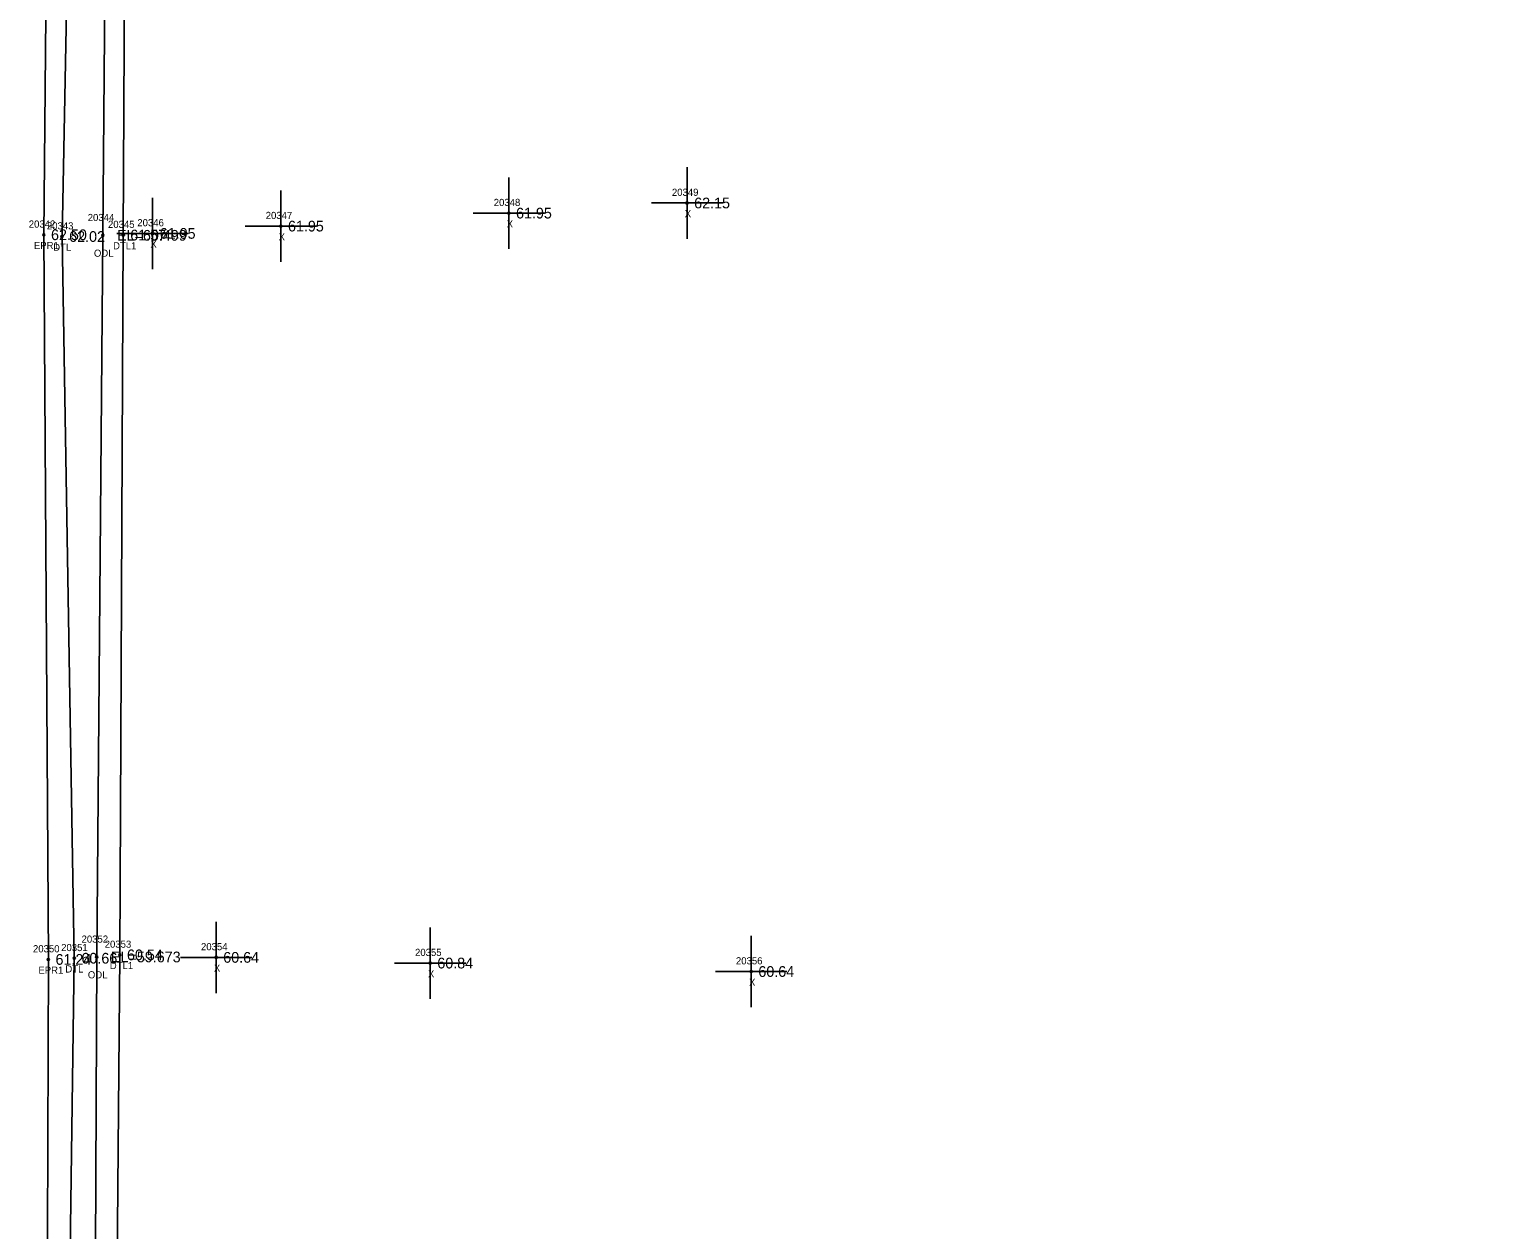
# Model space of a CAD drawing. Extents: x 2420351 to 2422725, y 845330 to 846558.
# Drawn here: x 2420969.7 to 2421174.5, y 845858.7 to 846026.9 of the extents above; entities that cross this region are included whole.
import ezdxf

# ---------------------------------------------------------------- set-up
doc = ezdxf.new("R2010")
doc.units = 0
for name, color, linetype in [('RD_EX_H2O', 7, 'Continuous'), ('RD_EX_H2O_txCode', 7, 'Continuous'), ('RD_EX_Misc', 7, 'Continuous'), ('RD_EX_Misc_txCode', 7, 'Continuous'), ('RD_EX_Road', 7, 'Continuous'), ('RD_EX_Road_txCode', 7, 'Continuous'), ('RD_EX_TX_H2O_ELEV', 7, 'Continuous'), ('RD_EX_TX_Misc_ELEV', 7, 'Continuous'), ('RD_EX_TX_Road_ELEV', 7, 'Continuous'), ('RD_SMD_Locator', 7, 'Continuous')]:
    doc.layers.add(name, color=color, linetype=linetype)

msp = doc.modelspace()

# ---------------------------------------------------------------- linework, layer by layer
at = {"layer": 'RD_EX_H2O'}
for points in [[(2420975.55, 846190.58), (2420976.37, 846105.11), (2420974.31, 845997.82), (2420976.03, 845896.74), (2420974.59, 845794.18), (2420975.37, 845743.63), (2420984.12, 845720.99), (2420999.91, 845711.18), (2421116.7, 845699.77), (2421177.35, 845696.01), (2421236.57, 845694.11), (2421292.07, 845694.75), (2421349.67, 845700.43), (2421411.57, 845706.56), (2421470.63, 845718.76), (2421529.96, 845732.93), (2421551.14, 845737.51), (2421602.97, 845753.33), (2421656.85, 845776.48), (2421724.45, 845805.15), (2421739.21, 845812.56)], [(2420980.17, 846190.47), (2420980.93, 846104.85), (2420980.02, 845997.99), (2420979.17, 845896.92), (2420978.72, 845794), (2420978.72, 845743.89), (2420987.58, 845724.3), (2421000.53, 845717.13), (2421117.24, 845704.33), (2421178.3, 845699.94), (2421237.1, 845697.97), (2421292.37, 845698.66), (2421349.43, 845702.84), (2421410.88, 845710.25), (2421469.94, 845721.7), (2421529.19, 845736.54), (2421550.26, 845742.27), (2421602, 845757.38), (2421655.89, 845778.44), (2421721.41, 845810.89), (2421742.22, 845823.45)], [(2420984.17, 846190.38), (2420983.45, 846105.14), (2420982.87, 845998.03), (2420982.41, 845897.21), (2420981.52, 845793.93), (2420982.23, 845744.07), (2420990.87, 845727.81), (2421002.71, 845721.72), (2421118.19, 845709.67), (2421178.8, 845706.59), (2421237.43, 845704.42), (2421292.29, 845705.88), (2421348.44, 845711.4), (2421408.11, 845718.43)]]:
    msp.add_lwpolyline(points, dxfattribs=at)
at = {"layer": 'RD_EX_Misc'}
for p, q in [((2421061.88, 845997.52), (2421061.88, 846007.52)), ((2421036.92, 845996.1), (2421036.92, 846006.1)), ((2420987, 845993.26), (2420987, 846003.26)), ((2421004.97, 845994.28), (2421004.97, 846004.28)), ((2421056.88, 846002.52), (2421066.88, 846002.52)), ((2421031.92, 846001.1), (2421041.92, 846001.1)), ((2420982, 845998.26), (2420992, 845998.26)), ((2420999.97, 845999.28), (2421009.97, 845999.28)), ((2420995.9, 845891.86), (2420995.9, 845901.86)), ((2421025.89, 845891.06), (2421025.89, 845901.06)), ((2421070.87, 845889.88), (2421070.87, 845899.88)), ((2420990.9, 845896.86), (2421000.9, 845896.86)), ((2421020.89, 845896.06), (2421030.89, 845896.06)), ((2421065.87, 845894.88), (2421075.87, 845894.88))]:
    msp.add_line(p, q, dxfattribs=at)
at = {"layer": 'RD_EX_Road'}
msp.add_lwpolyline([(2420972.5, 846190.42), (2420972.73, 846105.63), (2420971.77, 845998.07), (2420972.4, 845896.57), (2420972.04, 845794.22), (2420971.47, 845746.74), (2420974.33, 845731.55), (2420982.05, 845718.86), (2420998.34, 845708.25)], dxfattribs=at)
at = {"layer": 'RD_SMD_Locator'}
for centre in [(2421061.88, 846002.52), (2421036.92, 846001.1), (2420971.77, 845998.07), (2420982.87, 845998.03), (2420987, 845998.26), (2421004.97, 845999.28), (2420974.31, 845997.82), (2420980.02, 845997.99), (2420972.4, 845896.57), (2420976.03, 845896.74), (2420979.17, 845896.92), (2420982.41, 845897.21), (2420995.9, 845896.86), (2421025.89, 845896.06), (2421070.87, 845894.88)]:
    msp.add_circle(centre, 0.15, dxfattribs=at)

# ---------------------------------------------------------------- texts
at = {"layer": 'RD_EX_H2O_txCode'}
for s, p in [('20344', (2420977.91, 845999.99)), ('20343', (2420972.19, 845998.82)), ('20345', (2420980.75, 845999.03)), ('DTL', (2420973.07, 845995.82)), ('DTL1', (2420981.46, 845996.03)), ('ODL', (2420978.78, 845994.99)), ('20352', (2420977.05, 845898.92)), ('20351', (2420974.19, 845897.74)), ('20353', (2420980.29, 845898.21)), ('DTL1', (2420981, 845895.21)), ('DTL', (2420974.78, 845894.74)), ('ODL', (2420977.93, 845893.92))]:
    msp.add_text(s, height=1, dxfattribs=at).set_placement(p)
at = {"layer": 'RD_EX_Misc_txCode'}
for s, p in [('20349', (2421059.76, 846003.52)), ('20348', (2421034.8, 846002.1)), ('20346', (2420984.86, 845999.26)), ('20347', (2421002.85, 846000.28)), ('X', (2421061.56, 846000.52)), ('X', (2421004.66, 845997.28)), ('X', (2421036.61, 845999.1)), ('X', (2420986.69, 845996.26)), ('20354', (2420993.78, 845897.86)), ('20355', (2421023.77, 845897.06)), ('X', (2420995.59, 845894.86)), ('20356', (2421068.73, 845895.88)), ('X', (2421025.58, 845894.06)), ('X', (2421070.56, 845892.88))]:
    msp.add_text(s, height=1, dxfattribs=at).set_placement(p)
at = {"layer": 'RD_EX_Road_txCode'}
for s, p in [('20342', (2420969.65, 845999.07)), ('EPR1', (2420970.37, 845996.07)), ('20350', (2420970.24, 845897.57)), ('EPR1', (2420971, 845894.57))]:
    msp.add_text(s, height=1, dxfattribs=at).set_placement(p)
at = {"layer": 'RD_EX_TX_H2O_ELEV'}
for s, p in [('62.02', (2420975.31, 845997.07)), ('EL=60.499', (2420982.02, 845997.24)), ('61.57', (2420983.87, 845997.28)), ('60.54', (2420983.41, 845896.46)), ('60.66', (2420977.03, 845895.99)), ('EL=59.673', (2420981.17, 845896.17))]:
    msp.add_text(s, height=1.5, dxfattribs=at).set_placement(p)
at = {"layer": 'RD_EX_TX_Misc_ELEV'}
for s, p in [('62.15', (2421062.88, 846001.77)), ('61.95', (2421037.92, 846000.35)), ('61.95', (2420988, 845997.51)), ('61.95', (2421005.97, 845998.53)), ('60.64', (2420996.9, 845896.11)), ('60.84', (2421026.89, 845895.31)), ('60.64', (2421071.87, 845894.13))]:
    msp.add_text(s, height=1.5, dxfattribs=at).set_placement(p)
at = {"layer": 'RD_EX_TX_Road_ELEV'}
for s, p in [('62.50', (2420972.77, 845997.32)), ('61.24', (2420973.4, 845895.82))]:
    msp.add_text(s, height=1.5, dxfattribs=at).set_placement(p)

doc.saveas('drawing.dxf')
